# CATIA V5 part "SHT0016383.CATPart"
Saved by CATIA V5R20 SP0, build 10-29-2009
Part number: SHT0016383
Bounding box of the stored display mesh (mm): x -453 to 31, y 599.5 to 645.5, z 0.9 to 30.9
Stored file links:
  G:\冉\工作2022.11.18周五下午\6.张甲\3.A6\9.25  底支架2D图纸\2D\宽车副驾底支架\SHT0016383-A6宽车副司机座椅底支架左下板\SHT0016383.CATPart
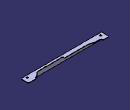
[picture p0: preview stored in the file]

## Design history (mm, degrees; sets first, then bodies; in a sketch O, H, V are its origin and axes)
Body1 (main body)
Body2 "SHT0016383-A6宽车副司机座椅底支架左下板"
  Solid1: solid without history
